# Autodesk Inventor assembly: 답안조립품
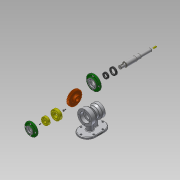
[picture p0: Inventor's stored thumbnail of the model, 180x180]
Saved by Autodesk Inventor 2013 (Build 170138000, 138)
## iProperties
Created: 2020-01
Part Number: 답안조립품
Document SubType Name: Assembly
Designer: Administrator
Author: Administrator
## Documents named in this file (13)
- C:\Users\Administrator\Desktop\700104V1017\답안조립품.iam
- C:\Users\Administrator\Desktop\700104V1017\본체.ipt
- C:\Users\Administrator\Desktop\700104V1017\뒤커버.ipt
- C:\Users\Administrator\Desktop\700104V1017\멈춤나사 M3.ipt
- C:\Users\Administrator\Desktop\700104V1017\베어링 6203.ipt
- C:\Users\Administrator\Desktop\700104V1017\베어링 6205.ipt
- C:\Users\Administrator\Desktop\700104V1017\볼트 M4.ipt
- C:\Users\Administrator\Desktop\700104V1017\스퍼기어.ipt
- C:\Users\Administrator\Desktop\700104V1017\앞커버.ipt
- C:\Users\Administrator\Desktop\700104V1017\오일 실 17 30 8.ipt
- C:\Users\Administrator\Desktop\700104V1017\오일 실 25 38 8.ipt
- C:\Users\Administrator\Desktop\700104V1017\축.ipt
- C:\Users\Administrator\Desktop\700104V1017\키 5 x 5 x 18.ipt
